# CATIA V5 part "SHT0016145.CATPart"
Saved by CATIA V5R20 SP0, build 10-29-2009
Part number: SHT0016145
Bounding box of the stored display mesh (mm): x -544.085 to -428.061, y -861 to -597, z 2.9 to 106.4
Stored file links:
  E:\宋国明\项目\02-福田A6-张甲\骨架钣金\2D\宽车主驾底支架\SHT0016145-宽车主驾驶前侧钣金\SHT0016145.CATPart
  C:\Users\hp\Desktop\SHT0016014-宽车主驾驶底部支架焊接总成\SHT0016014.CATPart

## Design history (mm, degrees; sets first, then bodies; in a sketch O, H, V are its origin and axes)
Body1 (main body)
Body2 "SHT0016145-宽车主驾驶前侧钣金"
  Solid1: solid without history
